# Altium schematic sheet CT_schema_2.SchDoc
size 276 x 169 mm
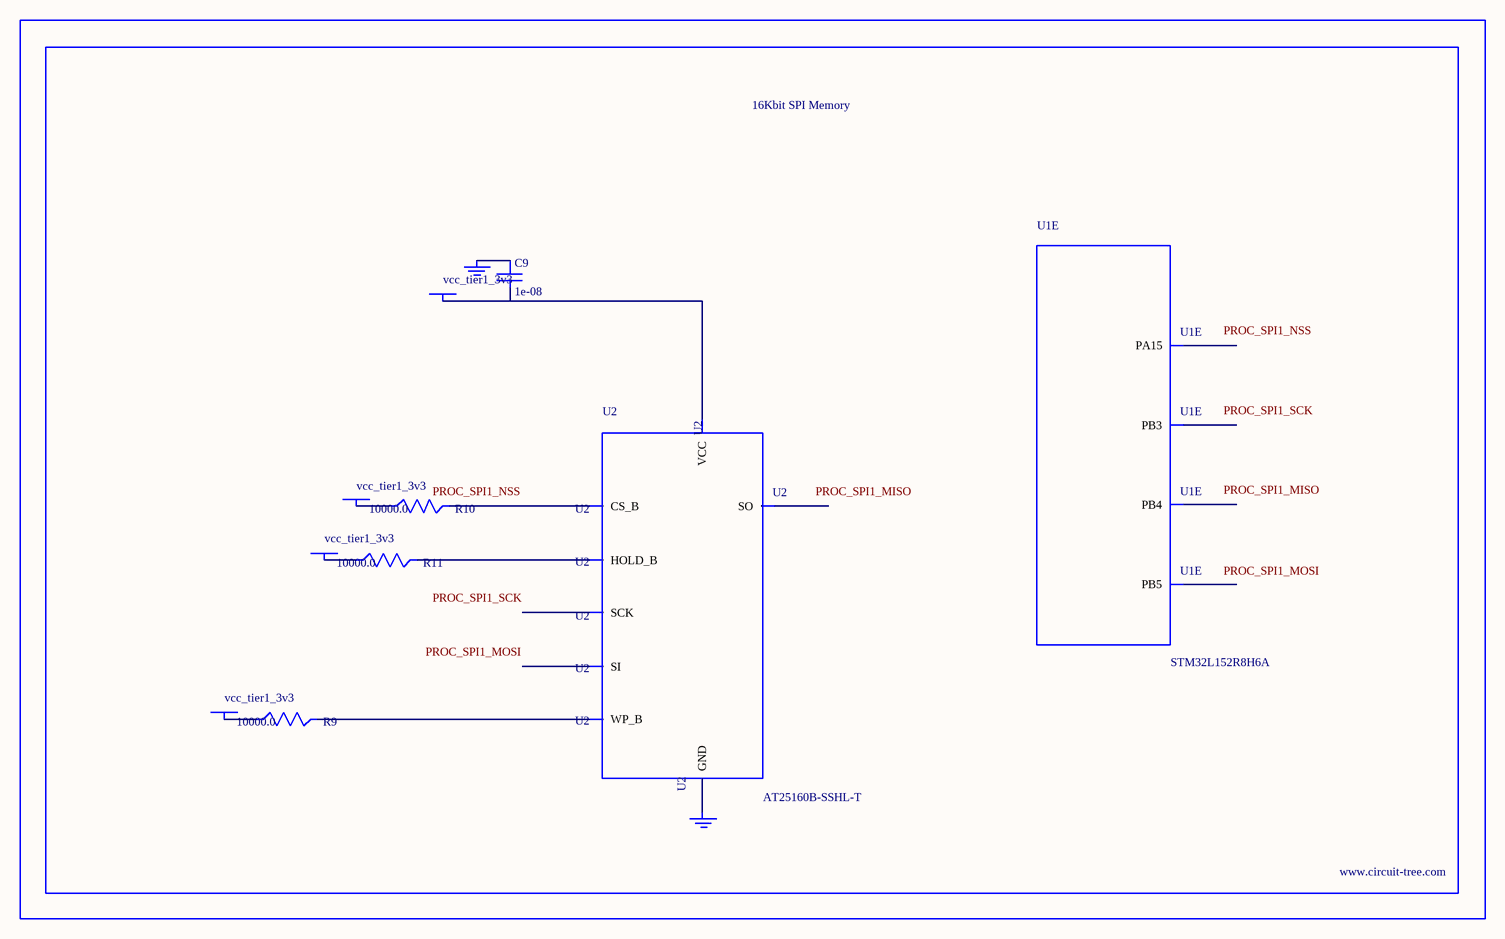
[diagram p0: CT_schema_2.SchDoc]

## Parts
BORDER1  (no value)
C9  1e-08  [C0402]
GND_INSTANCE_1_0  (no value)
GND_INSTANCE_1_1  (no value)
POWER_INSTANCE_1_0  vcc_tier1_3v3
POWER_INSTANCE_1_1  vcc_tier1_3v3
POWER_INSTANCE_1_2  vcc_tier1_3v3
POWER_INSTANCE_1_3  vcc_tier1_3v3
R9  10000.0  [R0603]
R10  10000.0  [R0603]
R11  10000.0  [R0603]
U1  STM32L152R8H6A  [TFBGA64]  (part E of 7)
U2  AT25160B-SSHL-T  [SOIC-8]

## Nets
NetC9_1: C9.1 GND_INSTANCE_1_0.0(GND)
NetC9_2: C9.2 POWER_INSTANCE_1_3.0(PWR) U2.8(VCC)
NetGND_INSTANCE_1_1_0: GND_INSTANCE_1_1.0(GND) U2.4(GND)
NetPOWER_INSTANCE_1_0_0: POWER_INSTANCE_1_0.0(PWR) R10.1
NetPOWER_INSTANCE_1_1_0: POWER_INSTANCE_1_1.0(PWR) R9.1
NetPOWER_INSTANCE_1_2_0: POWER_INSTANCE_1_2.0(PWR) R11.1
NetR9_2: R9.2 U2.3(WP_B)
NetR10_2: R10.2 U2.1(CS_B)
NetR11_2: R11.2 U2.7(HOLD_B)

Not connected (* = marked no-connect by the designer): U1 A4(PB4) A5(PB3) A6(PA15) C4(PB5); U2 2(SO) 5(SI) 6(SCK)

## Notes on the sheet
- Labels drawn without touching a wire or pin: PROC_SPI1_MISO, PROC_SPI1_MOSI, PROC_SPI1_NSS, PROC_SPI1_SCK

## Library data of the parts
BORDER1 = BORDER_PAGE1
C9 = C0402C103K3RAC
GND_INSTANCE_1_0 GND_INSTANCE_1_1 = GND
POWER_INSTANCE_1_0-POWER_INSTANCE_1_3 = PWR
R9-R11 = RC0603JR-0710KL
